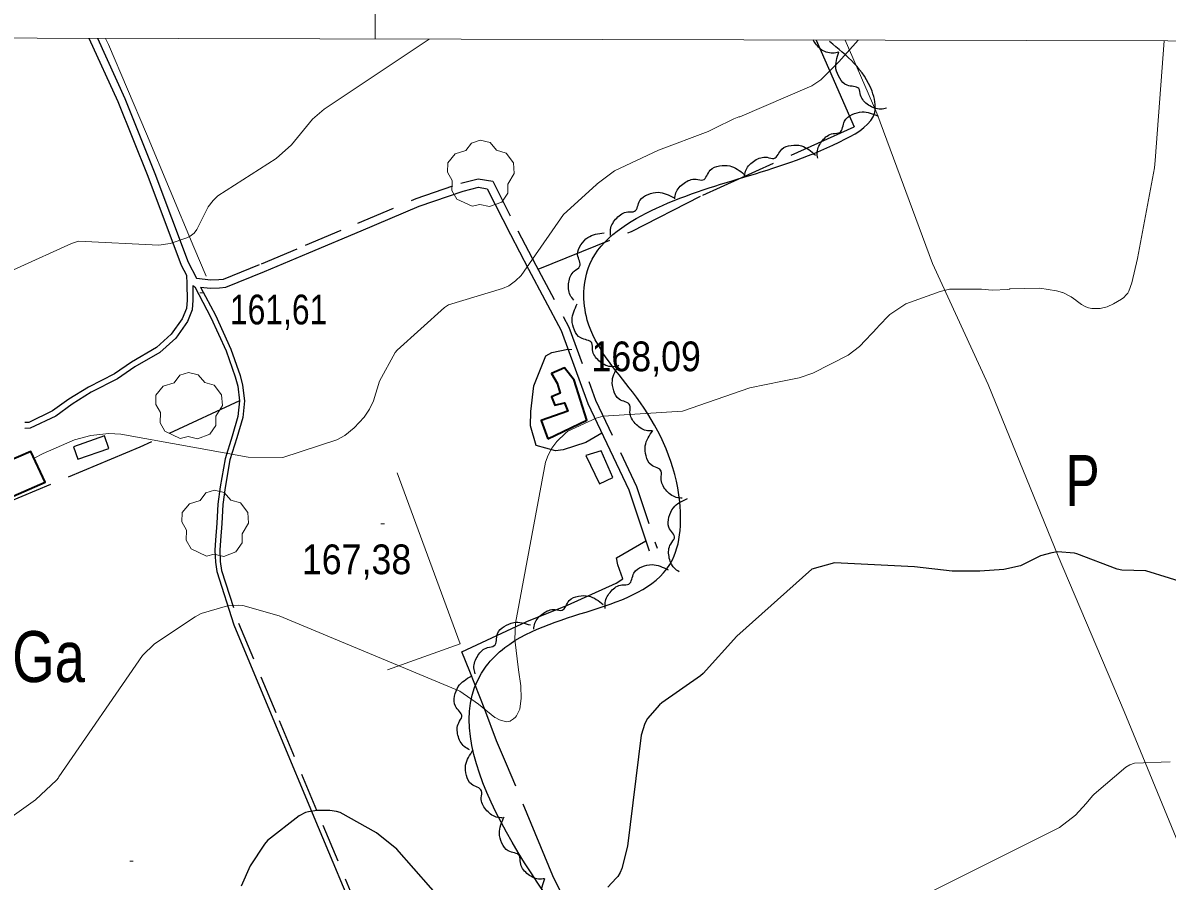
# Model space of a CAD drawing. Extents: x 480269 to 484877, y 4383588 to 4386804.
# Drawn here: x 482396.3 to 482733, y 4386204.2 to 4386456.6 of the extents above; entities that cross this region are included whole.
import ezdxf
from ezdxf.enums import TextEntityAlignment as Align

# ---------------------------------------------------------------- set-up
doc = ezdxf.new("R2010")
doc.units = 0
doc.header["$LTSCALE"] = 3.8
doc.linetypes.add('LONG_DASHED', pattern=[7.5, 6, -1.5])
doc.linetypes.add('MEDIUM_DASHED', pattern=[4.5, 3, -1.5])
for name, color, linetype, lineweight in [('1', 7, 'Continuous', 13), ('21', 7, 'Continuous', 25), ('25', 7, 'LONG_DASHED', 25), ('27', 7, 'Continuous', 25), ('29', 7, 'Continuous', 13), ('38', 7, 'Continuous', 25), ('47', 7, 'Continuous', 35), ('48', 7, 'MEDIUM_DASHED', 25), ('51', 7, 'Continuous', 13), ('7', 7, 'Continuous', 13), ('8', 7, 'Continuous', 25), ('9', 7, 'Continuous', 13)]:
    doc.layers.add(name, color=color, linetype=linetype, lineweight=lineweight)
doc.layers.add('31', color=7, linetype='Continuous')

msp = doc.modelspace()

# ---------------------------------------------------------------- linework, layer by layer
at = {"layer": '1'}
msp.add_line((482500, 4386451.92), (482500, 4386523.31), dxfattribs=at)
msp.add_lwpolyline([(480529.1, 4386456.6), (484105.5, 4386448.1), (484100.5, 4384135.8), (480523.1, 4384144.4)], close=True, dxfattribs=at)
at = {"layer": '21'}
msp.add_lwpolyline([(482566.01, 4386321.05), (482569.98, 4386322.93), (482566.51, 4386330.74), (482562, 4386329.44)], close=True, dxfattribs=at)
at = {"layer": '25'}
for points in [[(482629.77, 4386451.61), (482632.33, 4386445.77), (482640.91, 4386426.04)], [(482547.92, 4386384.18), (482575.43, 4386395.33), (482596.46, 4386405.99), (482640.91, 4386426.04)], [(482566.74, 4386335.94), (482562.01, 4386333.17), (482555.3, 4386331.08), (482553.1, 4386330.76), (482547.37, 4386332.38), (482545.67, 4386338.14), (482545.77, 4386342.37), (482546.71, 4386349.91), (482550.24, 4386358.71), (482552.02, 4386359.65), (482556.71, 4386360.7)], [(482460.05, 4386345.45), (482430.75, 4386331.82), (482391.79, 4386315.54), (482361.43, 4386303.79), (482338.21, 4386293.36), (482326.36, 4386289.82)], [(482557.27, 4386195.71), (482552.28, 4386205.76), (482538.64, 4386238.61), (482535.69, 4386245.45), (482532.24, 4386254.64), (482527.9, 4386265.83), (482525.5, 4386271.64), (482544.59, 4386280.56), (482556.56, 4386285.35), (482570.87, 4386291.82), (482572.91, 4386293.13), (482571.4, 4386297.28), (482571, 4386299.3), (482579.62, 4386304.33)]]:
    msp.add_lwpolyline(points, dxfattribs=at)
at = {"layer": '27'}
for points in [[(482473.95, 4385954.08), (482508.4, 4385970.53), (482563.99, 4386001.86), (482568.68, 4386019.88), (482572.6, 4386041.81), (482588.26, 4386061.4), (482584.34, 4386071.58), (482575.73, 4386084.11), (482544.41, 4386080.98), (482532.67, 4386087.24), (482479.43, 4386064.53), (482433.23, 4386041.03), (482430.88, 4386051.21), (482445.76, 4386058.26), (482505.26, 4386084.11), (482524.84, 4386097.43), (482510.74, 4386130.33), (482519.36, 4386132.68), (482543.63, 4386102.91), (482576.51, 4386111.53), (482587.47, 4386113.88), (482532.67, 4386267.41), (482538.15, 4386272.89), (482587.47, 4386298.74), (482589.04, 4386319.89), (482575.73, 4386348.09), (482562.42, 4386369.24), (482563.2, 4386385.69), (482582.78, 4386402.14), (482638.36, 4386422.5), (482646.98, 4386430.33), (482646.19, 4386436.6), (482633.68, 4386451.2)], [(482636.38, 4386448.05), (482634.63, 4386447.74), (482631.04, 4386448.95), (482628.84, 4386451.63)], [(482650.5, 4386431.57), (482648.75, 4386431.26), (482645.16, 4386432.47), (482642.84, 4386435.35), (482642.29, 4386437.32), (482638.87, 4386438.29), (482636.71, 4386440.35), (482635.59, 4386443.16), (482636.39, 4386448.06)], [(482630.21, 4386416.85), (482630.07, 4386418.62), (482631.65, 4386422.07), (482634.74, 4386424.08), (482636.77, 4386424.43), (482638.08, 4386427.73), (482640.35, 4386429.67), (482643.26, 4386430.49), (482648.04, 4386429.2)], [(482608.71, 4386411.7), (482609.15, 4386413.42), (482611.74, 4386416.19), (482615.32, 4386417.11), (482617.35, 4386416.79), (482619.64, 4386419.51), (482622.41, 4386420.62), (482625.43, 4386420.48), (482629.56, 4386417.73)], [(482588.13, 4386404.87), (482588.46, 4386406.61), (482590.89, 4386409.53), (482594.41, 4386410.65), (482596.45, 4386410.45), (482598.59, 4386413.3), (482601.29, 4386414.57), (482604.31, 4386414.6), (482608.59, 4386412.09)], [(482569.27, 4386394.13), (482569.26, 4386395.9), (482571.08, 4386399.24), (482574.31, 4386401.02), (482576.35, 4386401.22), (482577.89, 4386404.43), (482580.29, 4386406.2), (482583.25, 4386406.82), (482587.94, 4386405.19)], [(482558.43, 4386375.13), (482557.4, 4386376.58), (482556.98, 4386380.35), (482558.6, 4386383.66), (482560.16, 4386385), (482559.58, 4386388.51), (482560.53, 4386391.34), (482562.6, 4386393.54), (482567.37, 4386394.9)], [(482570.98, 4386355.59), (482569.2, 4386355.54), (482565.83, 4386357.27), (482563.96, 4386360.46), (482563.71, 4386362.5), (482560.47, 4386363.96), (482558.64, 4386366.31), (482557.95, 4386369.26), (482559.46, 4386373.98)], [(482581.52, 4386336.65), (482579.74, 4386336.76), (482576.54, 4386338.8), (482574.97, 4386342.14), (482574.91, 4386344.19), (482571.82, 4386345.94), (482570.21, 4386348.46), (482569.79, 4386351.45), (482571.73, 4386356.02)], [(482590.38, 4386316.85), (482588.61, 4386317.06), (482585.53, 4386319.26), (482584.14, 4386322.68), (482584.19, 4386324.74), (482581.2, 4386326.66), (482579.73, 4386329.26), (482579.48, 4386332.27), (482581.67, 4386336.72)], [(482589.45, 4386295.19), (482588.03, 4386296.25), (482586.46, 4386299.71), (482586.98, 4386303.36), (482588.05, 4386305.12), (482586.42, 4386308.28), (482586.45, 4386311.26), (482587.74, 4386314), (482591.86, 4386316.76)], [(482567.72, 4386284.36), (482567.68, 4386286.13), (482569.43, 4386289.5), (482572.62, 4386291.35), (482574.66, 4386291.59), (482576.14, 4386294.82), (482578.51, 4386296.64), (482581.46, 4386297.31), (482586.17, 4386295.78)], [(482546.67, 4386278.29), (482547, 4386280.03), (482549.42, 4386282.95), (482552.94, 4386284.08), (482554.98, 4386283.89), (482557.11, 4386286.74), (482559.81, 4386288.01), (482562.83, 4386288.05), (482567.11, 4386285.55)], [(482529.42, 4386265.18), (482529.08, 4386266.92), (482530.24, 4386270.54), (482533.08, 4386272.9), (482535.05, 4386273.47), (482535.97, 4386276.91), (482537.99, 4386279.1), (482540.79, 4386280.26), (482545.69, 4386279.54)], [(482527.72, 4386242.84), (482526.22, 4386243.78), (482524.37, 4386247.1), (482524.58, 4386250.78), (482525.5, 4386252.62), (482523.61, 4386255.63), (482523.39, 4386258.61), (482524.45, 4386261.44), (482528.32, 4386264.53)], [(482537.42, 4386222.83), (482535.65, 4386223.05), (482532.58, 4386225.28), (482531.22, 4386228.71), (482531.29, 4386230.76), (482528.31, 4386232.7), (482526.86, 4386235.31), (482526.62, 4386238.32), (482528.84, 4386242.76)], [(482549.84, 4386204.91), (482548.06, 4386204.82), (482544.66, 4386206.49), (482542.73, 4386209.64), (482542.44, 4386211.67), (482539.17, 4386213.07), (482537.29, 4386215.39), (482536.54, 4386218.32), (482537.96, 4386223.07)], [(482563.2, 4386187.79), (482561.44, 4386187.57), (482557.91, 4386188.97), (482555.75, 4386191.96), (482555.3, 4386193.97), (482551.93, 4386195.11), (482549.88, 4386197.28), (482548.92, 4386200.15), (482549.97, 4386204.99)]]:
    msp.add_spline(points, degree=3, dxfattribs=at)
at = {"layer": '29'}
for points in [[(482528.55, 4386402.69), (482524.01, 4386404.81), (482522.6, 4386407.35), (482522.7, 4386410.33), (482521.33, 4386412.74), (482521.37, 4386415.49), (482523.53, 4386418.09), (482526.72, 4386419.09), (482528.37, 4386421.28), (482530.94, 4386422.11), (482533.8, 4386421.46), (482535.75, 4386419.19), (482538.56, 4386418.37), (482540.69, 4386415.52), (482540.93, 4386412.39), (482539.05, 4386409.24), (482539.05, 4386406.56), (482537.23, 4386403.95), (482533.61, 4386402.61), (482530.84, 4386403.24)], [(482442.67, 4386334.39), (482438.13, 4386336.51), (482436.72, 4386339.05), (482436.82, 4386342.03), (482435.45, 4386344.44), (482435.49, 4386347.19), (482437.65, 4386349.79), (482440.84, 4386350.79), (482442.49, 4386352.98), (482445.06, 4386353.81), (482447.92, 4386353.16), (482449.87, 4386350.89), (482452.68, 4386350.07), (482454.81, 4386347.22), (482455.05, 4386344.09), (482453.17, 4386340.94), (482453.17, 4386338.26), (482451.35, 4386335.65), (482447.73, 4386334.31), (482444.96, 4386334.94)], [(482450.37, 4386299.79), (482445.83, 4386301.91), (482444.42, 4386304.45), (482444.52, 4386307.43), (482443.15, 4386309.84), (482443.19, 4386312.59), (482445.35, 4386315.19), (482448.54, 4386316.19), (482450.19, 4386318.38), (482452.76, 4386319.21), (482455.62, 4386318.56), (482457.57, 4386316.29), (482460.38, 4386315.47), (482462.51, 4386312.62), (482462.75, 4386309.49), (482460.87, 4386306.34), (482460.87, 4386303.66), (482459.05, 4386301.05), (482455.43, 4386299.71), (482452.66, 4386300.34)]]:
    msp.add_lwpolyline(points, close=True, dxfattribs=at)
at = {"layer": '38'}
for points in [[(482415.8, 4386452.12), (482424.28, 4386433.55), (482433.07, 4386411.57), (482442.93, 4386385.4), (482444.47, 4386382.44)], [(482418.26, 4386452.11), (482426.33, 4386434.43), (482435.15, 4386412.37), (482444.97, 4386386.31), (482447.44, 4386381.54)], [(482448.62, 4386378.93), (482451.51, 4386378.61), (482454.2, 4386378.68), (482456.03, 4386378.89), (482467.45, 4386383.51), (482480.44, 4386389.01), (482495.9, 4386395.47), (482512.92, 4386402.69), (482525.89, 4386407.14), (482530.39, 4386408.28), (482532.98, 4386407.83), (482539.8, 4386394.37), (482545.1, 4386384.24), (482554.71, 4386366.16), (482562.56, 4386344.73), (482574.63, 4386319.33), (482580.59, 4386301.39)], [(482444.47, 4386382.44), (482444.63, 4386379.86), (482444.67, 4386375.11), (482444.47, 4386372.61), (482443.26, 4386369.61), (482440.01, 4386365.05), (482435.64, 4386361.13), (482428.33, 4386356.89), (482423.28, 4386353.44), (482415.63, 4386349.49), (482409.89, 4386345.96), (482405.11, 4386342.49), (482398.07, 4386339.11), (482396.9, 4386339.09)], [(482446.36, 4386379.36), (482446.92, 4386379.01), (482451.67, 4386370.02), (482456.15, 4386360.16), (482458.85, 4386352.52), (482459.57, 4386349.77), (482460.05, 4386345.47), (482459.6, 4386340.83), (482457.93, 4386335.05), (482455.83, 4386328.43), (482454.38, 4386320.17), (482453.75, 4386315.12), (482453.4, 4386309.53), (482453.03, 4386304.48), (482452.86, 4386301.59), (482452.98, 4386298.05), (482453.39, 4386295.26), (482458.39, 4386279.6), (482470.43, 4386250.83), (482483.23, 4386220.1), (482494.88, 4386192.21)]]:
    msp.add_lwpolyline(points, dxfattribs=at)
at = {"layer": '38', "linetype": 'MEDIUM_DASHED'}
for points in [[(482447.44, 4386381.54), (482451.61, 4386381.08), (482454.02, 4386381.15), (482455.42, 4386381.3), (482466.51, 4386385.78), (482479.48, 4386391.28), (482494.94, 4386397.74), (482512.04, 4386404.99), (482525.19, 4386409.51), (482530.29, 4386410.8), (482534.62, 4386410.05), (482541.98, 4386395.5), (482547.28, 4386385.39), (482556.96, 4386367.17), (482564.83, 4386345.68), (482576.92, 4386320.25), (482582.93, 4386302.16)], [(482446.36, 4386379.36), (482446.4, 4386375.05), (482446.18, 4386372.21), (482444.78, 4386368.77), (482441.31, 4386363.89), (482436.66, 4386359.72), (482429.25, 4386355.43), (482424.17, 4386351.95), (482416.48, 4386347.99), (482410.85, 4386344.52), (482406, 4386341), (482398.48, 4386337.39), (482396.93, 4386337.36)], [(482448.62, 4386378.93), (482452.99, 4386370.66), (482457.51, 4386360.71), (482460.25, 4386352.95), (482461.01, 4386350.04), (482461.52, 4386345.48), (482461.04, 4386340.55), (482459.33, 4386334.62), (482457.25, 4386328.08), (482455.83, 4386319.96), (482455.21, 4386314.98), (482454.86, 4386309.43), (482454.49, 4386304.38), (482454.33, 4386301.57), (482454.44, 4386298.18), (482454.82, 4386295.59), (482459.76, 4386280.1), (482471.78, 4386251.4), (482484.58, 4386220.67), (482496.24, 4386192.73), (482506.11, 4386164.67), (482521.53, 4386136.18), (482535.04, 4386106.94), (482539.73, 4386094.27)]]:
    msp.add_lwpolyline(points, dxfattribs=at)
at = {"layer": '47'}
for points in [[(482550.82, 4386334.31), (482562.29, 4386339.83), (482558.58, 4386351.54), (482555.68, 4386355.22), (482551.86, 4386353.5), (482553.54, 4386350.7), (482554.46, 4386347.71), (482551.89, 4386346.65), (482552.88, 4386344.19), (482555.72, 4386344.91), (482556.74, 4386342.42), (482548.88, 4386339.69)], [(482380.42, 4386322.71), (482384.62, 4386313.63), (482402.93, 4386321.57), (482398.73, 4386330.57)]]:
    msp.add_lwpolyline(points, close=True, dxfattribs=at)
at = {"layer": '48'}
msp.add_lwpolyline([(482412.54, 4386328.27), (482421.62, 4386331.49), (482420.32, 4386335.16), (482411.24, 4386331.94)], close=True, dxfattribs=at)
at = {"layer": '51'}
for points in [[(482420.69, 4386452.1), (482421.5, 4386450.25), (482432.71, 4386424.06), (482446.65, 4386390.66), (482450.31, 4386382.13)], [(482638.32, 4386451.59), (482647.62, 4386430.08), (482664.03, 4386385.87), (482680.32, 4386350.25), (482700.95, 4386299.79), (482720.35, 4386254.06), (482737.04, 4386213.63), (482755.18, 4386171.6), (482774.92, 4386123.48), (482784.21, 4386101.54), (482793.23, 4386065.76), (482804.38, 4386014.76), (482814.66, 4385977.17), (482827.44, 4385919.58), (482834.05, 4385892.04), (482844.99, 4385841.67), (482856.12, 4385797.49), (482864.39, 4385756.22), (482876.84, 4385702.59), (482886.56, 4385661.96), (482888.55, 4385653.3)], [(482506.48, 4386324.31), (482525.06, 4386274.03), (482503.6, 4386266.36)]]:
    msp.add_lwpolyline(points, dxfattribs=at)
at = {"layer": '7'}
for p, q in [((482448.37, 4386377.27), (482449.37, 4386377.27)), ((482556.88, 4386360.61), (482557.88, 4386360.61)), ((482501.71, 4386309.33), (482502.71, 4386309.33)), ((482427.84, 4386210.09), (482428.84, 4386210.09))]:
    msp.add_line(p, q, dxfattribs=at)
at = {"layer": '8'}
for points in [[(482740.66, 4386291.11), (482726.71, 4386295.5), (482719.69, 4386295.68), (482718.32, 4386295.95), (482706.48, 4386300.51), (482705.8, 4386300.63), (482700.81, 4386301.03), (482699.11, 4386300.81), (482695.75, 4386299.84), (482689.84, 4386296.92), (482684.93, 4386295.89), (482677.96, 4386295.41), (482669.79, 4386295.41), (482658.73, 4386296.61), (482635.17, 4386297.82), (482628.51, 4386295.97), (482606.44, 4386276.28), (482596.48, 4386265.23), (482595.77, 4386264.62), (482584.35, 4386256.65), (482583.68, 4386256.04), (482580.09, 4386252.04), (482579.34, 4386250.58), (482578.22, 4386247.11), (482574.28, 4386214.51), (482572.55, 4386207.91), (482572.05, 4386206.78), (482571.4, 4386205.6), (482570.96, 4386205.02), (482568.45, 4386202.39)], [(482521.43, 4386196.53), (482506.37, 4386213.64), (482500.4, 4386218.43), (482489.68, 4386224.39), (482488.6, 4386224.7), (482486.64, 4386224.96), (482482.83, 4386224.95), (482480.42, 4386224.62), (482479.51, 4386224.34), (482477.64, 4386223.37), (482468.3, 4386216.13), (482467.41, 4386215.07), (482463.27, 4386208.74), (482460.61, 4386202.68)]]:
    msp.add_lwpolyline(points, dxfattribs=at)
at = {"layer": '9'}
for points in [[(482515.93, 4386451.88), (482484.99, 4386431.27), (482481.59, 4386428.36), (482475.38, 4386420.81), (482470.89, 4386416.72), (482453.74, 4386405.78), (482452.32, 4386404.45), (482450.86, 4386402.53), (482447.55, 4386395.91), (482446.76, 4386394.79), (482445.61, 4386393.9), (482444.63, 4386393.41), (482439.68, 4386391.79), (482436.36, 4386391.29), (482412.68, 4386392.43), (482410.69, 4386391.76), (482378.63, 4386377.25)], [(482399.63, 4386328.65), (482402.35, 4386330.02), (482411.56, 4386333.98), (482416.35, 4386335.26), (482421.66, 4386335.82), (482425.16, 4386335.64), (482462.67, 4386328.95), (482472.84, 4386328.79), (482472.88, 4386328.8), (482488.69, 4386333.96), (482491.08, 4386335.26), (482493.87, 4386337.5), (482496.75, 4386340.7), (482498.35, 4386343.06), (482499.52, 4386345.45), (482501.32, 4386351.27), (482505.91, 4386359.65), (482506.43, 4386360.34), (482520.4, 4386372.92), (482521.54, 4386373.67), (482537.49, 4386378.49), (482539.32, 4386379.34), (482541.34, 4386380.73), (482542.97, 4386382.34), (482555.41, 4386400.33), (482565.03, 4386409), (482565.1, 4386409.05), (482565.31, 4386409.27), (482570.39, 4386413.12), (482583.36, 4386419.21), (482597.99, 4386424.67), (482599.93, 4386425.68), (482605.49, 4386428.46), (482607.04, 4386429), (482607.31, 4386429.05), (482628.47, 4386438.11), (482631.11, 4386439.87), (482636.45, 4386445.18), (482642.08, 4386451.54), (482642.14, 4386451.58)], [(482538.51, 4386251.07), (482539.72, 4386251.27), (482539.84, 4386251.31), (482540.71, 4386251.93), (482541.3, 4386252.47), (482541.58, 4386252.83), (482542.56, 4386254.8), (482542.95, 4386258.01), (482542.97, 4386258.06), (482542.88, 4386261.56), (482542.89, 4386261.61), (482542.13, 4386266.31), (482542.13, 4386266.34), (482541.1, 4386275.25), (482541.29, 4386280.11), (482550.16, 4386327.42), (482550.89, 4386329.51), (482552, 4386331.53), (482553.41, 4386333.47), (482555.96, 4386335.96), (482556.66, 4386336.52), (482564.99, 4386340.39), (482567.08, 4386340.96), (482590.39, 4386342.39), (482610.2, 4386349.3), (482619.85, 4386351.27), (482624.71, 4386352.2), (482628.77, 4386353.57), (482639.13, 4386358.94), (482642.53, 4386361.43), (482647.88, 4386367.1), (482648.01, 4386367.32), (482651.45, 4386370.87), (482656.13, 4386373.96), (482666.27, 4386377.66), (482669, 4386378.33), (482678.36, 4386378.36), (482681.51, 4386378), (482686.19, 4386378.27), (482686.65, 4386378.35), (482686.75, 4386378.4), (482686.77, 4386378.41), (482686.79, 4386378.41), (482695.59, 4386378.64), (482700.5, 4386377.84), (482702.26, 4386377.35), (482702.27, 4386377.34), (482702.29, 4386377.32), (482704.79, 4386376.05), (482706.19, 4386375.08), (482706.23, 4386375.02), (482707.79, 4386373.86), (482709.09, 4386373.11), (482709.92, 4386372.83), (482710.83, 4386372.66), (482713.27, 4386372.66), (482713.33, 4386372.67), (482715.34, 4386373.15), (482717.27, 4386373.99), (482719.61, 4386375.39), (482720.25, 4386375.87), (482721.01, 4386376.62), (482721.42, 4386377.13), (482721.79, 4386377.76), (482722.61, 4386380.2), (482724.29, 4386387.31), (482729.33, 4386414.04), (482729.47, 4386416.14), (482732.19, 4386451.36)], [(482383.77, 4386216.56), (482400.09, 4386228.1), (482406.23, 4386233.9), (482406.84, 4386234.63), (482406.93, 4386234.79), (482406.93, 4386234.81), (482406.93, 4386234.83), (482406.97, 4386234.84), (482431.51, 4386270.58), (482435.06, 4386274.04), (482447.05, 4386281.98), (482448.82, 4386282.89), (482456.57, 4386285.21), (482459.9, 4386285.33), (482461.06, 4386285.25), (482471.74, 4386282.28), (482524.94, 4386260.08), (482530.39, 4386256.22), (482530.4, 4386256.22), (482530.43, 4386256.21), (482535.21, 4386252.37), (482535.25, 4386252.36), (482535.3, 4386252.34), (482536.57, 4386251.65), (482538.29, 4386251.11), (482538.51, 4386251.07)], [(482642.3, 4386190.48), (482701.4, 4386219.99), (482706.05, 4386223.58), (482709.16, 4386227.01), (482711.04, 4386229.24), (482711.6, 4386229.79), (482720.83, 4386237.73), (482722.02, 4386238.41), (482723.42, 4386238.91), (482733.93, 4386239.33)]]:
    msp.add_lwpolyline(points, dxfattribs=at)

# ---------------------------------------------------------------- texts
at = {"layer": '31'}
for s, width, p in [('P', 0.75, (482708.16, 4386314.54)), ('Ga', 0.8, (482403.9, 4386262.74))]:
    msp.add_text(s, height=15, dxfattribs=dict(at, width=width)).set_placement(p, align=Align.CENTER)
at = {"layer": '7'}
for s, width, p in [('161,61', 0.8, (482457.28, 4386367.96)), ('168,09', 0.9, (482563.63, 4386354.18)), ('167,38', 0.9, (482478.42, 4386294.48))]:
    msp.add_text(s, height=8.75, dxfattribs=dict(at, width=width)).set_placement(p)

doc.saveas('drawing.dxf')
